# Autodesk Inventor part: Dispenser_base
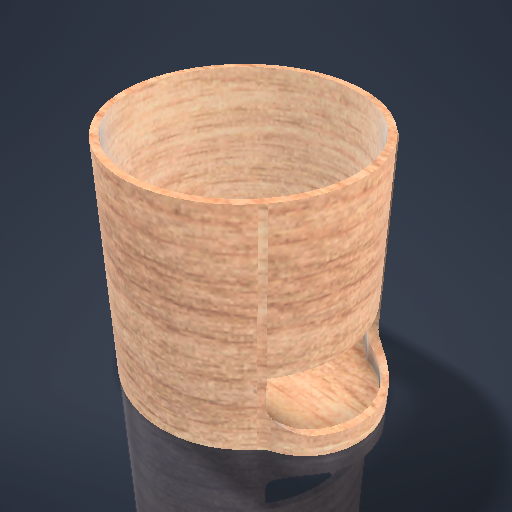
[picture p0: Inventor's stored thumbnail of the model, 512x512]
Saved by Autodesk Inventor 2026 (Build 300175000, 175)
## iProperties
Created: 2026-02
Part Number: Dispenser_base
Material: Madera (abedul)
Document SubType Name: Modeling
Designer: balle
Density: 0.55 g/cm^3
Appearance: Abedul - Natural pulido
Author: balle
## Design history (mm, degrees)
sketch "Boceto1"
  geometry: C1 r 50 at (0, 0); 1 further point
  constraints: 1 centre point, 1 coincident
  dimensions: "d0" = 100 diameter of C1
extrude "Extrusión1" new body sketch "Boceto1" distance "d1" = 100; taper "d2" = 0 deg
feature "Vaciado1" dims "d9" = 3
sketch "Boceto2"
  geometry: L1 (33, 30)-(3, 30); L2 (3, 30)-(3, -30); L3 (3, -30)-(33, -30); L4 (33, -30)-(33, 30); L5 (0, -50)-(0, 50) reference; 2 further points
  constraints: 8 end point, 2 parallel, 1 horizontal, 1 midpoint, 1 perpendicular
  dimensions: "d3" = 30 distance of L3.end L2.end; "d4" = 60 distance of L2.end L1.end; "d5" = 3 distance between parallel lines of L5 L2; "d6" = 30 distance from line of L1 point (0, 0)
extrude "Extrusión2" cut sketch "Boceto2" distance "d7" = 50; taper "d8" = 0 deg
sketch "Boceto3"
  geometry: L1 (0, 60)-(3.82, 60) reference; L2 (0, 0)-(3.82, 0) reference; L3 (2.291, 57)-(3.321, 57); L4 (2.291, 3)-(3.321, 3); A1 r 50 centre (-36.18, 30) between (3.82, 60) and (3.82, 0) reference; A2 r 47 centre (-36.18, 30) between (0, 60) and (0, 0) reference; A3 r 31.623 centre (-6.18, 30) between (3.82, 0) and (3.82, 60); A4 r 28.623 centre (-6.18, 30) between (3.321, 3) and (3.321, 57); 3 further points
  constraints: 6 point on circle, 4 end point, 2 centre point, 2 parallel
  dimensions: "d11" = 30 distance of point (-36.18, 30) A3.centre; "d12" = 3 distance between parallel lines of L1 L3; "d13" = 3 radial gap between concentric circles of A3 A4; "d14" = 3 distance between parallel lines of L2 L4
extrude "Extrusión3" join sketch "Boceto3" distance "d15" = 3; taper "d16" = 0 deg
extrude "Extrusión4" join sketch "Boceto3" distance "d17" = 7; taper "d18" = 0 deg
fillet "Empalme1" dims "d19" = 10
fillet "Empalme2" dims "d22" = 10
fillet "Empalme3" dims "d21" = 10
node "Sólido1"
